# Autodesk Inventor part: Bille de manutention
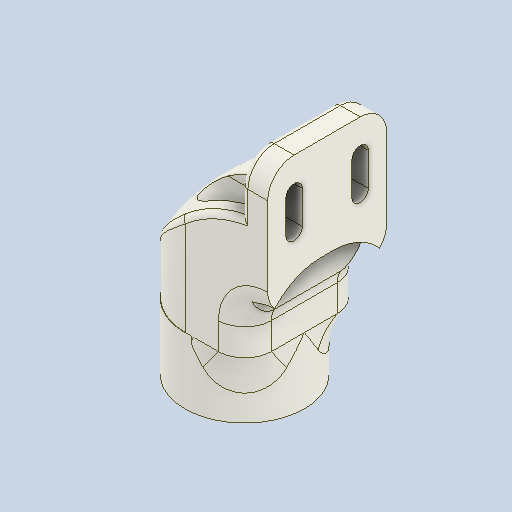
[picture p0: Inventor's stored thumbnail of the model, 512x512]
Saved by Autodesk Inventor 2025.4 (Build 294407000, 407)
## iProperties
Created: 2026-06
Part Number: Bille de manutention
Material: Generic
Document SubType Name: Modeling
Designer: AdminForWorker
Density: 1 g/cm^3
Appearance: Default
Title: Bille de manutention v16
Author: AdminForWorker
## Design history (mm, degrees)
feature "Body2"
feature "Body3"
body "Solid1"
body "Solid2"
